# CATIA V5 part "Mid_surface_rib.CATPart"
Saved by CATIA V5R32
Part number: Part1
Bounding box of the stored display mesh (mm): x -50 to 50, y -7.836 to 79.398, z 0 to 79.208
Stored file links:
  D:\PROJECTS\Project 2022\CATIA V5 6R 2022\Resources\Part Files\c17_catia_v6_6r2022_prt\Mid_surface_rib.CATPart
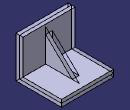
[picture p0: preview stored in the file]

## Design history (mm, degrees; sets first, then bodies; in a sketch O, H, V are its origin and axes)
Body1 (main body)
  Sketch1 on yz-plane, origin (0, 0, 0), H (0, 1, 0), V (0, 0, 1)
    line L1 (5.5044, 79.2082) -> (-7.8364, 79.2082)
    line L2 (-7.8364, 79.2082) -> (-7.8364, 0)
    point P3 (-7.8364, 0)
    line L3 (-7.8364, 0) -> (79.3978, 0)
    line L4 (79.3978, 0) -> (79.3978, 12.9983)
    line L5 (79.3978, 12.9983) -> (5.5044, 12.9983)
    line L6 (5.5044, 12.9983) -> (5.5044, 79.2082)
    horizontal: L1 H, L5 H, L3 H
    coincidence: P3 H
    vertical: L4 V, L6 V, L2 V
    parallelism: L5 L3
  Pad1: profile Sketch1, direction (-1, 0, 0), length 50, mirrored extent
  Sketch2 on yz-plane, origin (0, 0, 0), H (0, 1, 0), V (0, 0, 1)
    line L1 (56.7612, 12.9983) -> (5.5044, 61.9732)
    point P1 (56.7612, 12.9983)
    point P2 (5.5044, 61.9732)
    reference projected line E1 (5.5044, 18.7088) -> (5.5044, 69.2026) from edge [face of Pad1 from Sketch1.L6 | start face of Pad1]
    reference projected line E2 (79.0467, 12.9983) -> (8.5173, 12.9983) from edge [face of Pad1 from Sketch1.L5 | start face of Pad1]
    coincidence: P2 E1, P1 E2
  Stiffener1: ExtendedProfile Sketch2, ThicknessTop 0, ThicknessValue 13
  MidSurface1: InputSolid Stiffener1, FacePairs ({midsurfacefacepair Face1 face of Pad1 from Sketch1.L6, Face2 face of Pad1 from Sketch1.L2}; {midsurfacefacepair Face1 face of Pad1 from Sketch1.L5, Face2 face of Pad1 from Sketch1.L3}), OffsetRatio 0.5
  MidSurface2: InputSolid Stiffener1, FacePairs {midsurfacefacepair Face1 face of Stiffener1, Face2 face of Stiffener1}, OffsetRatio 0.5, LimitingMidSurface MidSurface1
